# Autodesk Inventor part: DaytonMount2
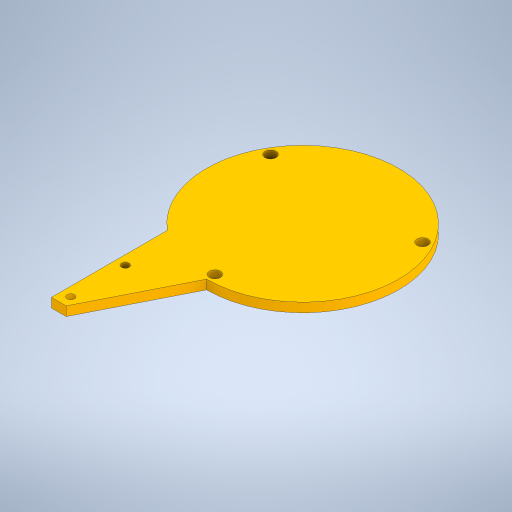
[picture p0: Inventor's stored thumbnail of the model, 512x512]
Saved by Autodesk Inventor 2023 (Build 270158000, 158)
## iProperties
Created: 2023-06
Part Number: DaytonMount2
Material: Generic
Document SubType Name: Modeling
Designer: Admin
Density: 1 g/cm^3
Appearance: Default
Author: Admin
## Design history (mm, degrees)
sketch "Sketch1" dims "d18" = 4, "d43" = 95
  geometry: L1 (25.5, -43)-(25.5, -58); L2 (17, -25.5)-(17, -30.5); L3 (17, -30.5)-(6, -30.5); L4 (6, -30.5)-(6, -25.5); L5 (6, -25.5)-(17, -25.5); L6 (0, -153)-(0, 0); L7 (0, -153)-(0, 0); L8 (51, 0)-(51, -153); L9 (60.249, 0)-(60.249, -153); L10 (25.5, -28)-(25.5, 0); L11 (0, 0)-(51, 0); L12 (0, 0)-(60.249, 0); L13 (51, -153)-(0, -153); L14 (60.249, -153)-(0, -153); L15 (46, -60.5)-(35, -60.5); L16 (35, -60.5)-(35, -55.5); L17 (46, -55.5)-(46, -60.5); L18 (51, -33)-(59, -33); L19 (51, -75)-(51, -33); L20 (59, -33)-(59, -75); L21 (59, -75)-(51, -75); L22 (25.5, -58)-(25.5, -73); L23 (25.5, -73)-(25.5, -88); L24 (17, -60.5)-(6, -60.5); L25 (17, -55.5)-(17, -60.5); L26 (6, -55.5)-(17, -55.5); L27 (6, -60.5)-(6, -55.5); L28 (17, -90.5)-(6, -90.5); L29 (17, -85.5)-(17, -90.5); L30 (6, -85.5)-(17, -85.5); L31 (35, -85.5)-(46, -85.5); L32 (46, -90.5)-(35, -90.5); L33 (46, -85.5)-(46, -90.5); L34 (35, -90.5)-(35, -85.5); L35 (6, -90.5)-(6, -85.5); L36 (25.5, -28)-(25.5, -43); L37 (35, -30.5)-(35, -25.5); L38 (46, -25.5)-(46, -30.5); L39 (35, -25.5)-(46, -25.5); L40 (46, -30.5)-(35, -30.5); L41 (54, -40.5)-(25.5, -40.5); L42 (35, -55.5)-(46, -55.5); L43 (59, -95.729)-(59, -33); L44 (51, -33)-(59, -33); L45 (25.5, -83.5)-(51, -33); C1 r 2.5 at (25.5, -28); C2 r 2 at (54, -68); C3 r 2.5 at (25.5, -58); C4 r 2.5 at (25.5, -73); C5 r 2.5 at (25.5, -88); C6 r 3 at (25.5, -88); C7 r 3 at (66.636, -159.25); C8 r 3 at (-15.636, -159.25); C9 r 3 at (-15.636, -159.25); C10 r 3 at (66.636, -159.25); C11 r 3 at (25.5, -88); C12 r 2 at (54, -38.5); C13 r 2 at (54, -68); A1 r 52 centre (25.5, -135.5) between (25.5, -83.5) and (59, -95.729); 5 further points
  constraints: 82 end point, 14 centre point, 10 vertical alignment, 9 coincident, 8 collinear, 7 parallel, 5 concentric, 5 horizontal, 4 perpendicular, 4 point on line, 3 equal radius, 2 point on circle, 2 vertical, 1 midpoint, 1 tangent, 65 other
  dimensions: "d4" = 5 distance between parallel lines of L3 L5; "d5" = 11 distance between parallel lines of L4 L2; "d6" = 153 distance between parallel lines of L14 L11; "d7" = 51 distance between parallel lines of L6 L8; "d8" = 15 distance of L10.start L1.start; "d9" = 28 distance of L10.start L10.end; "d10" = 8 distance between parallel lines of L20 L8; "d11" = 5 diameter of C1; "d12" = 33 distance between parallel lines of L11 L18; "d13" = 42 distance of L18.end L20.end; "d14" = 6 distance between parallel lines of L6 L4; "d15" = 30 distance of L2.end L24.start; "d16" = 29 distance of L2.end L38.end; "d17" = 3 distance from line of L8 point (54, -38.5); "d19" = 29.5 distance of C2.centre point (54, -38.5); "d44" = 6 diameter of C6; "d47" = 360 deg dimension on point (25.5, -135.5) C6.centre (derived); "d61" = 52 radius of A1
extrude "Extrusion1" new body sketch "Sketch1" distance "d63" = 5; taper "d64" = 0 deg
body "Solid1"
other parameters: "d42" = 104
